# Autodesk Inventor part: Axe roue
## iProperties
Shininess: 64.0
Length Units: 11269
Angle Units: 11279
Time Units: 11290
Mass Units: 11283
Length Display Precision: 3
Angle Display Precision: 2
Compacted: True
Part Number: Axe roue
Document SubType Name: Modeling
Created: 2003-05
Material: Acier doux
Designer: Philippe
Density: 0.0
Volumn: 0.0
Area: 0.0
PropertySet Name: Model Information
Control State: 0
Master: False
Checked Out: False
Author: Philippe
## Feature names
1. Révolution1 [Revolution]
2. Perçage1 [Hole]
3. Chanfrein1 [Chamfer]
